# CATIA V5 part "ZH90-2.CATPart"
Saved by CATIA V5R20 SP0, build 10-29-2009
Part number: ZH902
Bounding box of the stored display mesh (mm): x 0 to 259, y -20 to 55, z -29.7 to 15
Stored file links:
  C:\Users\Utente\Desktop\IO LAVORO\3D X SITO CF\X SITO\PLASTICA\ZH90\ZH90-2.CATPart
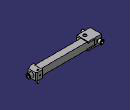
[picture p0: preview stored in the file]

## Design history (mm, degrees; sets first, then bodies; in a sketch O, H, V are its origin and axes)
Set1
  DatumSurface1 to DatumSurface16 "_ZH90/2_head"
  DatumSurface17 to DatumSurface34 "_ZH90/2_screw1"
  DatumSurface35 to DatumSurface55 "_ZH90/2_hand"
  DatumSurface56 to DatumSurface73 "_ZH90/2_screw2"
  DatumSurface74 to DatumSurface94 "_ZH90/2_he"
  DatumSurface95 to DatumSurface109 "_ZH90/2_screw3"
  DatumSurface110 to DatumSurface117 "_ZH90/2_stift1"
  DatumSurface118 to DatumSurface127 "_ZH90/2_stift2"
Body1 (main body)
